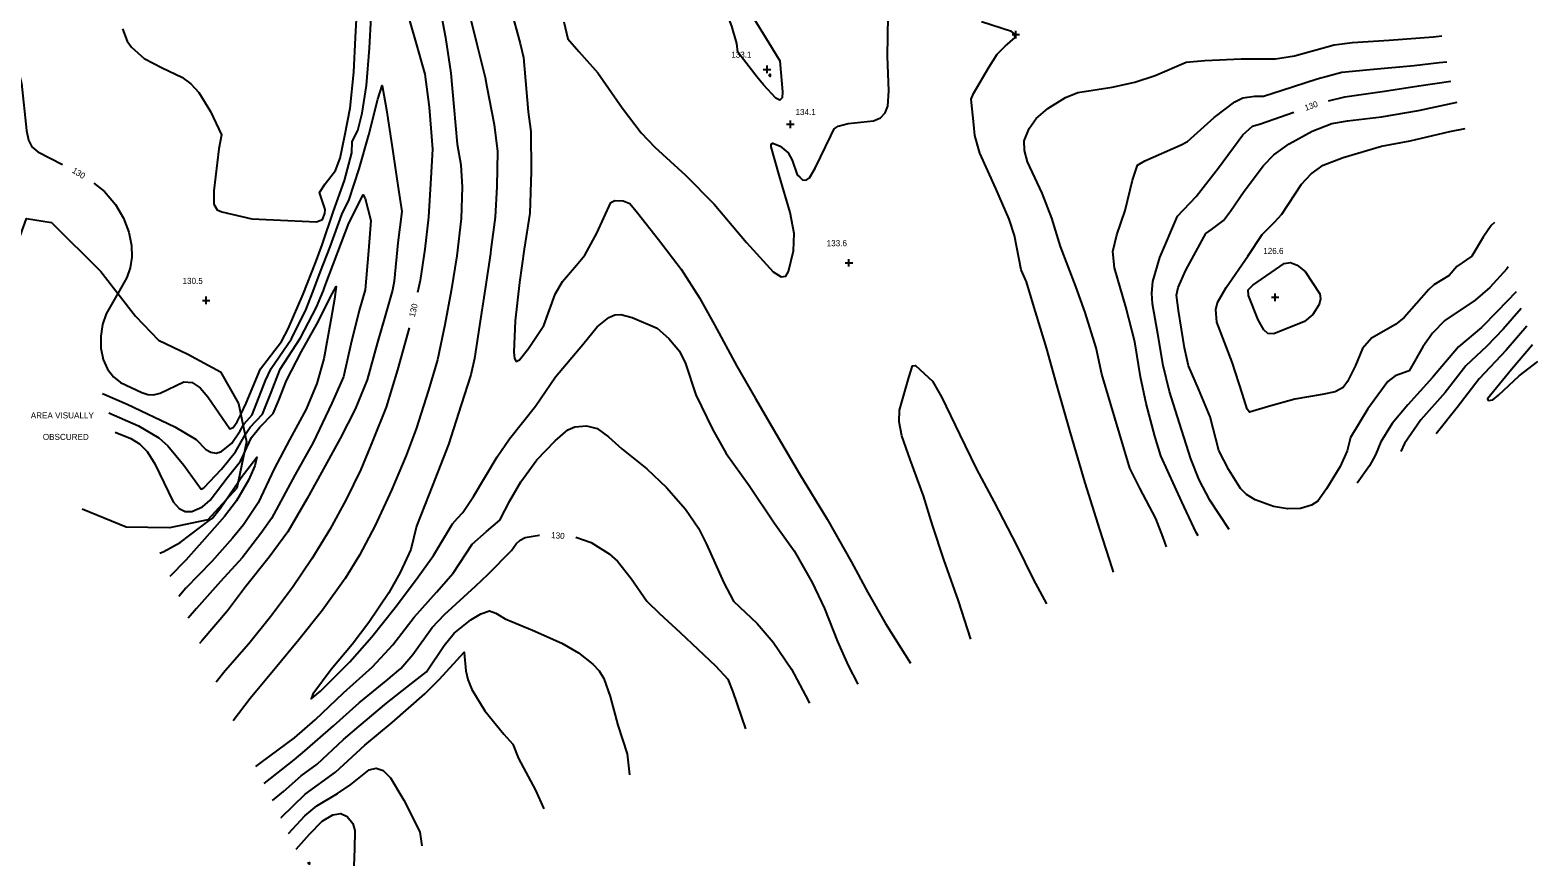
# Model space of a CAD drawing. Extents: x 1475150 to 2003689, y 770235 to 1112803.
# Drawn here: x 2002493.7 to 2002991.4, y 770562.1 to 770837.9 of the extents above; entities that cross this region are included whole.
import ezdxf

# ---------------------------------------------------------------- set-up
doc = ezdxf.new("R2010")
doc.units = 0
for name, color, linetype in [('RD_DTM_Major1', 7, 'Continuous'), ('RD_DTM_Major1_Lbl', 7, 'Continuous'), ('RD_DTM_Major2', 7, 'Continuous'), ('RD_DTM_Minor1', 7, 'Continuous'), ('RD_DTM_Minor2', 7, 'Continuous'), ('RD_DTM_Obscure', 7, 'Continuous'), ('RD_DTM_Spot_Elev', 7, 'Continuous'), ('RD_TX_Misc1', 7, 'Continuous')]:
    doc.layers.add(name, color=color, linetype=linetype)

msp = doc.modelspace()

# ---------------------------------------------------------------- linework, layer by layer
at = {"layer": 'RD_DTM_Major1'}
for points in [[(2002465.72, 770861.55), (2002468.59, 770858.95), (2002472.79, 770853.64), (2002478.26, 770844), (2002482.78, 770837.46), (2002487.68, 770830.27), (2002489.58, 770825.77), (2002490.82, 770820.44), (2002492.47, 770804.83), (2002493.14, 770801.64), (2002494.31, 770799.47), (2002496.27, 770797.81), (2002504.44, 770793.62)], [(2002563.25, 770711.12), (2002565.02, 770714.78), (2002569.71, 770726.13), (2002576.65, 770735.2), (2002578.88, 770739.39), (2002583.81, 770750.77), (2002587.92, 770761.13), (2002590.06, 770767.11), (2002593.86, 770778.22), (2002597.49, 770788.32), (2002599.88, 770797.47), (2002600.05, 770801.23), (2002601.83, 770804.88), (2002603.35, 770810.59), (2002604.73, 770819.72), (2002605.7, 770831.98), (2002606.26, 770842.36)], [(2002617.72, 770845.32), (2002620.86, 770834.63), (2002624.02, 770823.43), (2002625.4, 770812.48), (2002626.48, 770798.68), (2002625.98, 770789.07), (2002625.17, 770776.26), (2002624.04, 770765.63), (2002622.5, 770755.28), (2002621.63, 770751.31)], [(2002922.31, 770814.62), (2002927.69, 770815.95), (2002940.76, 770817.81), (2002952.06, 770819.59), (2002962.64, 770821.09)], [(2002889.51, 770673.17), (2002883.12, 770682.8), (2002879.63, 770689.56), (2002876.8, 770696.44), (2002873.16, 770708.19), (2002869.86, 770718.64), (2002867.73, 770727.25), (2002865.96, 770737.69), (2002864.17, 770747.58), (2002863.96, 770751.18), (2002864.27, 770754.99), (2002866.58, 770762.96), (2002872.44, 770776.59), (2002878.56, 770783.06), (2002885.93, 770792.51), (2002894.01, 770803.41), (2002897.2, 770806.21), (2002899.9, 770807.07), (2002906.4, 770809.32), (2002910.89, 770810.93)], [(2002514.75, 770787.49), (2002518.22, 770784.71), (2002521.88, 770780.45), (2002524.53, 770775.86), (2002526.25, 770771.23), (2002527.12, 770766.86), (2002527.23, 770762.98), (2002526.69, 770759.51), (2002525.62, 770756.36), (2002522.64, 770751.01)], [(2002984.23, 770751.58), (2002978.01, 770745.04), (2002972.83, 770739.83), (2002965.25, 770733.42), (2002960.88, 770728.34), (2002956.64, 770723.25), (2002948.43, 770714.26), (2002943.3, 770708.14), (2002939.54, 770702.04), (2002937.82, 770697.79), (2002935.86, 770694.12), (2002931.76, 770688.38)], [(2002618.78, 770739.65), (2002618.5, 770738.49), (2002615.03, 770725.84), (2002611.23, 770713.47), (2002606.69, 770702.3), (2002602.91, 770692.95), (2002597.98, 770682.98), (2002592.63, 770673.16), (2002586.72, 770663.45), (2002580.27, 770654.01), (2002573.06, 770644.26), (2002565.87, 770635.35), (2002558.06, 770626.45), (2002555.13, 770622.75)], [(2002570.96, 770589.25), (2002580.87, 770597.05), (2002584.36, 770600.1), (2002593.8, 770608.32), (2002602.36, 770615.94), (2002611.21, 770623.19), (2002616.06, 770627.26), (2002620.03, 770631.82), (2002626.41, 770640.73), (2002630.49, 770645.06), (2002640.71, 770654.39), (2002644.86, 770658.36), (2002652.59, 770666.21), (2002654.2, 770668.44), (2002655.45, 770669.58), (2002657.13, 770670.48), (2002661.78, 770671.23), (2002661.89, 770671.23)], [(2002673.87, 770670.57), (2002678.86, 770668.78), (2002684.82, 770665.12), (2002687.6, 770662.68), (2002692.13, 770656.98), (2002697.33, 770649.49), (2002701.45, 770645.39), (2002708.3, 770639.12), (2002719.94, 770628.17), (2002723.98, 770623.72), (2002725.68, 770619.5), (2002729.82, 770607.35)], [(2002585.26, 770562.99), (2002585.95, 770563.26), (2002585.78, 770562.42)]]:
    msp.add_lwpolyline(points, dxfattribs=at)
at = {"layer": 'RD_DTM_Major2'}
msp.add_lwpolyline([(2002522.64, 770751.01), (2002522.33, 770750.46), (2002518.83, 770744.31), (2002517.6, 770740.83), (2002517.01, 770736.99), (2002517.09, 770733.02), (2002517.83, 770729.26), (2002519.21, 770726.01), (2002521.19, 770723.52), (2002523.56, 770721.68), (2002530.6, 770718.3), (2002532.54, 770717.68), (2002534.48, 770717.54), (2002536.59, 770718.08), (2002544.44, 770721.82), (2002547.21, 770721.64), (2002549.88, 770719.85), (2002552.33, 770716.94), (2002559.67, 770706.33), (2002560.72, 770706.81), (2002562.09, 770708.7), (2002563.25, 770711.12)], dxfattribs=at)
at = {"layer": 'RD_DTM_Minor1'}
for points in [[(2002733.66, 770822.46), (2002727.28, 770830.71), (2002726.97, 770833.49), (2002725.31, 770839.24), (2002720.81, 770851.06), (2002716.15, 770863.55), (2002714.46, 770869.94), (2002714.39, 770871.74), (2002714.85, 770872.46), (2002715.79, 770871.99), (2002718.91, 770867.69), (2002724.33, 770857.65), (2002730.87, 770844.67), (2002738.41, 770832.36), (2002741.23, 770827.87), (2002742.1, 770817.58), (2002741.93, 770815.65), (2002741.22, 770814.83), (2002739.84, 770815.51), (2002735.81, 770819.85), (2002733.66, 770822.46)], [(2002524.2, 770838.4), (2002525.73, 770834.31), (2002527.13, 770832.32), (2002531.38, 770828.61), (2002537.26, 770825.56), (2002543.79, 770822.4), (2002546.8, 770820.19), (2002549.4, 770817.36), (2002553.3, 770811.13), (2002556.88, 770803.37), (2002556.04, 770798.8), (2002554.4, 770784.87), (2002554.39, 770780.55), (2002555.48, 770778.68), (2002556.99, 770777.93), (2002566.87, 770775.64), (2002578.77, 770775.07), (2002588.26, 770774.67), (2002590.18, 770775.47), (2002591.03, 770777.38), (2002591.07, 770778.77), (2002589.27, 770784.37), (2002591.1, 770787.27), (2002594.54, 770791.6), (2002596.03, 770795.65), (2002597.59, 770803.14), (2002599.32, 770812.16), (2002600.58, 770824.09), (2002601.09, 770835.53), (2002601.72, 770847.48)], [(2002628.75, 770846.52), (2002630.82, 770835.53), (2002632.56, 770823.79), (2002633.53, 770812.59), (2002634.62, 770800.37), (2002635.85, 770793.54), (2002636.34, 770786.11), (2002636.02, 770775.73), (2002634.57, 770763.49), (2002632.67, 770751.91), (2002630.59, 770740.69), (2002628.16, 770729.17), (2002625.24, 770719.1), (2002621.18, 770706.4), (2002617.84, 770697.56), (2002613, 770686.15), (2002607.65, 770674.42), (2002602.47, 770664.7), (2002597.72, 770656.92), (2002590.24, 770646.46), (2002582.46, 770636.71), (2002574.59, 770627.2), (2002566.3, 770617.39), (2002560.78, 770609.94)], [(2002638.66, 770843.59), (2002641.15, 770833.27), (2002643.92, 770822.31), (2002644.47, 770819.21), (2002646.86, 770806.85), (2002647.95, 770797.88), (2002647.76, 770786.3), (2002647.21, 770776.26), (2002645.8, 770765.54), (2002645.65, 770764.28), (2002643.89, 770752.53), (2002642.03, 770740.49), (2002640.37, 770729.53), (2002639.13, 770724.14), (2002636.03, 770714.29), (2002631.77, 770701.14), (2002626.58, 770687.66), (2002621.29, 770674.2), (2002619.34, 770666.47), (2002615.9, 770658.93), (2002612.13, 770652.22), (2002605.56, 770642.38), (2002599.98, 770635.2), (2002593.12, 770626.91), (2002587.06, 770618.75), (2002586.46, 770617.18), (2002589.59, 770619.8), (2002599.19, 770629.47), (2002606.48, 770637.75), (2002614.22, 770647.43), (2002621.29, 770656.74), (2002626.91, 770664.53), (2002633.18, 770675.03), (2002634.81, 770676.82), (2002636.51, 770678.69), (2002640.02, 770683.98), (2002647.86, 770697.08), (2002652, 770703.04), (2002660.49, 770713.8), (2002667.18, 770723.56), (2002676.2, 770734.21), (2002680.91, 770740), (2002684.69, 770743.13), (2002686.67, 770743.96), (2002688.65, 770744.12), (2002692.45, 770743.14), (2002700.67, 770739.56), (2002704.55, 770736.22), (2002708.01, 770731.99), (2002710.04, 770727.88), (2002713.41, 770717.63), (2002718.94, 770706.27), (2002723.52, 770698.22), (2002731.08, 770687.61), (2002739.34, 770675.33), (2002745.91, 770666.04), (2002751.82, 770655.64), (2002755.94, 770647.08), (2002760.21, 770636.19), (2002763.71, 770628.26), (2002766.88, 770622.06)], [(2002652.28, 770845.24), (2002655.46, 770833.5), (2002656.56, 770828.97), (2002657.24, 770821.17), (2002658.12, 770811), (2002659.03, 770804.47), (2002659.1, 770791.33), (2002658.61, 770777.58), (2002656.83, 770765.7), (2002655.25, 770754.65), (2002653.78, 770741.97), (2002653.33, 770731.63), (2002653.56, 770729.55), (2002654.19, 770728.61), (2002655.28, 770729.16), (2002658.18, 770732.85), (2002663.3, 770740.46), (2002667.06, 770750.75), (2002669.44, 770755.01), (2002674.02, 770760.39), (2002676.83, 770763.73), (2002680.77, 770770.94), (2002685.4, 770781.05), (2002686.7, 770781.72), (2002689.42, 770781.6), (2002691.72, 770780.69), (2002694.22, 770777.7), (2002701.17, 770768.86), (2002708.6, 770759.11), (2002714.69, 770749.58), (2002719.65, 770740.68), (2002727, 770727.06), (2002733.18, 770716.41), (2002739.87, 770704.84), (2002747.69, 770691.51), (2002756.85, 770676.53), (2002764.74, 770662.52), (2002770.25, 770652.33), (2002776.08, 770642.15), (2002784.31, 770628.99)], [(2002669.85, 770840.66), (2002671.24, 770835.1), (2002674.86, 770830.92), (2002681.12, 770823.87), (2002689.13, 770812.34), (2002695.39, 770804.07), (2002699.92, 770799.31), (2002710.06, 770790.1), (2002719.48, 770780.48), (2002730.16, 770767.86), (2002738.93, 770758.18), (2002741.58, 770756.49), (2002743.17, 770756.74), (2002744.09, 770758.27), (2002745.73, 770765.11), (2002745.92, 770770.78), (2002744.63, 770777.8), (2002740.95, 770790.05), (2002738.27, 770799.46), (2002738.36, 770800.32), (2002738.89, 770800.64), (2002741.28, 770799.67), (2002743.92, 770797.46), (2002745.26, 770795.04), (2002746.93, 770790.22), (2002747.8, 770789.42), (2002748.71, 770788.54), (2002749.88, 770788.43), (2002750.98, 770789.21), (2002752.88, 770792.44), (2002758.07, 770803.07), (2002759.07, 770805.35), (2002760.43, 770806.31), (2002763.69, 770807.13), (2002772.09, 770807.99), (2002774.45, 770808.99), (2002775.99, 770810.69), (2002776.82, 770812.91), (2002777.17, 770817.96), (2002776.71, 770829.22), (2002776.95, 770842.66)], [(2002851.27, 770659.08), (2002851, 770660.16), (2002846.78, 770673.13), (2002841.94, 770688.53), (2002837.08, 770705.01), (2002832.77, 770720.43), (2002829.21, 770733.12), (2002824.79, 770747.51), (2002822.61, 770754.84), (2002820.84, 770758.83), (2002818.64, 770770.14), (2002816.92, 770775.61), (2002812.45, 770785.65), (2002807.22, 770797.35), (2002805.5, 770803.19), (2002805.21, 770806.73), (2002804.31, 770815.16), (2002805.11, 770817), (2002810.27, 770825.82), (2002812.93, 770830.04), (2002815.52, 770832.66), (2002818.85, 770835.51), (2002818.6, 770836.75), (2002817.68, 770837.54), (2002807.74, 770840.67)], [(2002868.82, 770667.4), (2002867.72, 770670.48), (2002865.33, 770676.72), (2002859.97, 770686.77), (2002856.69, 770693.42), (2002853.3, 770704.76), (2002850.19, 770715.2), (2002847.49, 770724.35), (2002845.64, 770733.09), (2002841.92, 770744.74), (2002838.86, 770753.33), (2002833.83, 770766.54), (2002830.99, 770775.84), (2002827.82, 770784.11), (2002822.9, 770794.5), (2002821.91, 770798.2), (2002821.88, 770801.45), (2002823.51, 770805.45), (2002825.82, 770808.76), (2002829.69, 770812.06), (2002835.5, 770815.73), (2002839.58, 770817.36), (2002850.91, 770819.1), (2002858.38, 770820.73), (2002865.03, 770822.99), (2002875.26, 770827.42), (2002881.46, 770827.94), (2002893.51, 770828.47), (2002899.63, 770828.45), (2002904.77, 770828.43), (2002911.05, 770829.48), (2002924.21, 770833.07), (2002930.24, 770833.89), (2002942.32, 770834.64), (2002956.91, 770835.76), (2002959.65, 770836.1)], [(2002879.23, 770671.02), (2002878.66, 770672.15), (2002873.88, 770682.31), (2002866.9, 770697.44), (2002865, 770703.93), (2002862.09, 770714.74), (2002860.21, 770723.47), (2002858.33, 770735.1), (2002855.34, 770746.65), (2002851.6, 770759.52), (2002851.12, 770764.84), (2002852.42, 770770.36), (2002855.12, 770778.46), (2002857.56, 770788.39), (2002859.27, 770793.35), (2002861.7, 770794.81), (2002873.65, 770800.12), (2002875.79, 770801.19), (2002884.51, 770809.11), (2002891.36, 770814.34), (2002894.06, 770815.64), (2002897.94, 770816.17), (2002900.8, 770816.21), (2002907.05, 770818.13), (2002918.51, 770821.83), (2002926.66, 770824.09), (2002937.11, 770825.04), (2002950.56, 770826.31), (2002958.87, 770827.31), (2002961.36, 770827.51)], [(2002737.62, 770823.19), (2002738.03, 770823.37), (2002738.02, 770822.7), (2002737.62, 770823.19)], [(2002564, 770707.45), (2002564.34, 770708.02), (2002566.96, 770711.02), (2002571.39, 770722.29), (2002573.25, 770726.28), (2002579.97, 770736.1), (2002584.81, 770745.85), (2002587.17, 770751.75), (2002589.54, 770758.25), (2002592.77, 770766.45), (2002596.56, 770777.15), (2002599.05, 770782.1), (2002602.33, 770792.13), (2002605.57, 770803.41), (2002608.45, 770815.17), (2002609.93, 770819.67), (2002611.3, 770811.6), (2002613.15, 770800.07), (2002615.13, 770786.63), (2002616.43, 770778.04), (2002615.1, 770767.74), (2002613.93, 770755.13), (2002613.35, 770752.11), (2002610.93, 770743.7), (2002608.25, 770734.48), (2002604.93, 770722.58), (2002600.99, 770712.82), (2002596.1, 770703.15), (2002591.14, 770694.17), (2002585.2, 770683.31), (2002578.83, 770672.34), (2002572.6, 770663.95), (2002564.82, 770654.23), (2002558.88, 770646.32), (2002550.5, 770636.45), (2002549.57, 770635.46)], [(2002981.65, 770759.87), (2002981.17, 770759.15), (2002975.53, 770753.01), (2002970.69, 770748.87), (2002960.66, 770742.1), (2002956.59, 770737.88), (2002953.38, 770733.46), (2002948.92, 770725.46), (2002944.3, 770723.88), (2002941.84, 770722), (2002935.23, 770712.96), (2002929.5, 770703.48), (2002928.41, 770699.08), (2002926.17, 770693.97), (2002921.66, 770686.56), (2002918.81, 770682.45), (2002916.64, 770681.17), (2002913.08, 770680.1), (2002908.71, 770679.91), (2002904.11, 770680.73), (2002898.08, 770682.92), (2002895.17, 770684.66), (2002893.21, 770686.61), (2002889.39, 770692.86), (2002886.05, 770699.25), (2002883.25, 770710.31), (2002879.33, 770719.53), (2002876.1, 770727.19), (2002874.81, 770733.12), (2002872.76, 770745.38), (2002872.09, 770750.43), (2002872.62, 770753.01), (2002875.24, 770758.72), (2002881.78, 770770.81), (2002883.67, 770772.19), (2002887.6, 770775.09), (2002889.95, 770778.21), (2002894.43, 770784.81), (2002900.88, 770793.25), (2002904.29, 770796.83), (2002909.35, 770800.43), (2002916.94, 770804.64), (2002923.41, 770807.12), (2002928.6, 770807.98), (2002939.79, 770809.3), (2002951.96, 770811.46), (2002964.74, 770814.21)], [(2002977.11, 770774.46), (2002976.01, 770773.44), (2002973.39, 770769.58), (2002969.61, 770763.32), (2002964.7, 770759.95), (2002962.1, 770756.99), (2002957.11, 770753.86), (2002955.4, 770752.32), (2002947.29, 770743.07), (2002944.41, 770740.8), (2002936.48, 770736.3), (2002933.48, 770732.9), (2002931.16, 770727.3), (2002928.61, 770722.02), (2002927.09, 770720.05), (2002924.51, 770718.58), (2002920.15, 770717.7), (2002911.21, 770716.16), (2002902.47, 770713.76), (2002896.26, 770711.88), (2002895.45, 770712.88), (2002893.85, 770717.82), (2002890.52, 770728.37), (2002885.46, 770741.51), (2002885.06, 770745.76), (2002885.66, 770748.03), (2002888.48, 770753.04), (2002895.67, 770763.4), (2002900.4, 770770.47), (2002904.49, 770774.6), (2002906.88, 770777.25), (2002913.4, 770787.11), (2002916.56, 770790.57), (2002920.55, 770793.36), (2002927.12, 770795.87), (2002939.74, 770799.66), (2002949.28, 770801.45), (2002962.29, 770804.45), (2002967.44, 770805.53)], [(2002564.65, 770704.33), (2002564.77, 770704.55), (2002566.33, 770706.94), (2002570.47, 770711.21), (2002573.32, 770718.32), (2002576.26, 770726.09), (2002583.01, 770736.36), (2002588.19, 770746.52), (2002590.51, 770752.03), (2002590.94, 770753.32), (2002595.28, 770764.62), (2002598.9, 770774.25), (2002603.7, 770783.61), (2002604.36, 770782.37), (2002606.19, 770775.14), (2002605.43, 770765.09), (2002604.32, 770752.25), (2002602.33, 770745.42), (2002599.6, 770734.33), (2002597.11, 770723.56), (2002593.35, 770714.79), (2002587.19, 770701.86), (2002581.14, 770691.03), (2002573.42, 770676.81), (2002569.92, 770671.79), (2002563.67, 770663.72), (2002556.54, 770655.97), (2002548.63, 770647.03), (2002545.9, 770643.84)], [(2002897.28, 770753.77), (2002907.64, 770760.88), (2002909.76, 770761.23), (2002911.99, 770760.41), (2002914.62, 770758.34), (2002919.42, 770750.86), (2002919.61, 770749.21), (2002919.22, 770747.44), (2002917.16, 770744.06), (2002914.36, 770741.81), (2002904.21, 770737.67), (2002902.3, 770737.8), (2002900.91, 770739), (2002899.08, 770742.34), (2002895.9, 770750.38), (2002895.82, 770752.25), (2002897.28, 770753.77)], [(2002564.27, 770698.04), (2002565.27, 770700.18), (2002566.83, 770703.54), (2002569.53, 770706.95), (2002573.99, 770711.4), (2002575.82, 770715.78), (2002578.31, 770722.34), (2002583.31, 770731.93), (2002588.32, 770740.85), (2002593.44, 770750.95), (2002594.76, 770753.36), (2002594.18, 770749.19), (2002593.1, 770742.85), (2002590.65, 770729.42), (2002588.39, 770721.28), (2002584.85, 770712.87), (2002579.3, 770702.71), (2002574.27, 770693.18), (2002568.96, 770681.9), (2002564.14, 770674.69), (2002560.55, 770670.28), (2002553.69, 770662.6), (2002545.16, 770653.81), (2002542.77, 770650.99)], [(2002985.94, 770746.07), (2002980, 770739.2), (2002974.51, 770733.69), (2002967.63, 770727.14), (2002960.76, 770718.38), (2002952.74, 770709.27), (2002947.33, 770701.5), (2002946.2, 770698.9)], [(2002987.77, 770740.21), (2002980.9, 770732.32), (2002972.04, 770722.87), (2002964.72, 770713.45), (2002957.88, 770704.74)], [(2002989.66, 770734.12), (2002982.73, 770725.94), (2002974.79, 770716.27), (2002975.03, 770715.72), (2002976.55, 770715.89), (2002978.42, 770717.48), (2002985.26, 770723.82), (2002991.39, 770728.55)], [(2002804.22, 770636.89), (2002800.16, 770649.62), (2002795.36, 770663.2), (2002791.56, 770674.51), (2002788.59, 770684.25), (2002784.16, 770696.2), (2002781.44, 770704.09), (2002780.59, 770708.71), (2002780.71, 770712.5), (2002783.74, 770723.34), (2002784.95, 770727.14), (2002785.98, 770727.27), (2002791.57, 770722.08), (2002794.69, 770716.7), (2002800.44, 770704.56), (2002806.14, 770693.02), (2002811.8, 770682.35), (2002819.43, 770667.72), (2002824.83, 770656.73), (2002829.17, 770648.6)], [(2002568.18, 770594.9), (2002569.93, 770596.17), (2002580.96, 770604.31), (2002587.78, 770610.31), (2002597.17, 770619.2), (2002606.72, 770627.74), (2002613.47, 770635.03), (2002620.52, 770644.14), (2002627.9, 770652.41), (2002633.35, 770658.76), (2002639.59, 770668.31), (2002644.33, 770672.44), (2002648.81, 770676.24), (2002652.07, 770682.54), (2002655.66, 770688.91), (2002661, 770696.07), (2002666.99, 770702.38), (2002671.23, 770706), (2002673.51, 770706.99), (2002677.37, 770707.34), (2002680.85, 770706.51), (2002684.62, 770703.67), (2002688.98, 770699.7), (2002697.28, 770693.16), (2002703.76, 770687.04), (2002709.99, 770679.81), (2002714.35, 770673.54), (2002716.98, 770668.28), (2002722.65, 770655.53), (2002725.93, 770649.44), (2002733.71, 770642.09), (2002739, 770635.89), (2002745.04, 770627.05), (2002749.69, 770618.37), (2002751.01, 770615.76)], [(2002562.38, 770688.77), (2002563.39, 770690.24), (2002568.56, 770696.97), (2002567.89, 770694.19), (2002565.83, 770689.42), (2002561.81, 770682.63), (2002557.92, 770677.41), (2002551.31, 770669.94), (2002545.15, 770663.02), (2002539.88, 770657.61)], [(2002536.53, 770665.26), (2002537.9, 770665.84), (2002543.23, 770668.86), (2002552.85, 770676.05), (2002553.75, 770676.78), (2002556.39, 770680.08), (2002558.08, 770682.52)], [(2002573.69, 770583.69), (2002577.32, 770586.64), (2002583.23, 770591.84), (2002588.49, 770595.72), (2002597.18, 770603.84), (2002602.27, 770608.19), (2002611.39, 770615.78), (2002619.55, 770622.27), (2002624.59, 770626.13), (2002630.41, 770634.87), (2002633.72, 770638.86), (2002639.13, 770643.36), (2002642.44, 770645.34), (2002645.31, 770646.23), (2002647.41, 770645.53), (2002650.52, 770643.67), (2002659.56, 770639.92), (2002669.2, 770635.63), (2002674.68, 770632.43), (2002679.51, 770628.71), (2002681.52, 770626.5), (2002683.13, 770623.98), (2002685.19, 770617.99), (2002687.76, 770608.52), (2002690.75, 770599.07), (2002691.53, 770592.14)], [(2002576.47, 770578.04), (2002576.56, 770578.11), (2002584.55, 770585.77), (2002594.55, 770593.03), (2002604.21, 770601.98), (2002613.18, 770609.42), (2002623.98, 770618.91), (2002628.84, 770623.73), (2002636.95, 770632.66), (2002637.02, 770632.4), (2002637.5, 770626.47), (2002638.19, 770623.57), (2002639.47, 770620.28), (2002643.78, 770613.25), (2002650.11, 770605.58), (2002653, 770602.25), (2002654.91, 770597.58), (2002660.51, 770587.05), (2002663.29, 770580.92)], [(2002579.05, 770572.81), (2002584.4, 770578.58), (2002588.31, 770581.86), (2002595.16, 770586.03), (2002599.58, 770588.92), (2002605.64, 770593.79), (2002607.89, 770594.3), (2002610.27, 770593.53), (2002612.68, 770591.13), (2002617.1, 770583.82), (2002622.4, 770573.33), (2002622.98, 770568.73)], [(2002581.58, 770567.66), (2002585.98, 770572.51), (2002590.08, 770576.85), (2002593.62, 770578.94), (2002596.27, 770579.41), (2002598.34, 770578.35), (2002600.28, 770576.08), (2002600.87, 770573.77), (2002600.83, 770567.74), (2002600.51, 770562.1)]]:
    msp.add_lwpolyline(points, dxfattribs=at)
at = {"layer": 'RD_DTM_Minor2'}
msp.add_line((2002558.08, 770682.52), (2002562.38, 770688.77), dxfattribs=at)
for points in [[(2002517.57, 770718.03), (2002525.75, 770714.55), (2002541.5, 770707.01), (2002548.49, 770702.83), (2002551.73, 770699.56), (2002553.35, 770698.6), (2002555.11, 770698.27), (2002556.92, 770698.83), (2002560.25, 770701.62), (2002562.99, 770705.71), (2002564, 770707.45)], [(2002519.71, 770711.62), (2002529.51, 770707.39), (2002536.22, 770703.34), (2002539.16, 770700.76), (2002544.5, 770694.32), (2002550.2, 770686.47), (2002551.09, 770686.84), (2002556.87, 770693.03), (2002561.49, 770698.72), (2002564.65, 770704.33)], [(2002521.83, 770705.26), (2002526.95, 770703.17), (2002529.81, 770701.42), (2002532.32, 770698.88), (2002534.84, 770694.84), (2002540.95, 770682.25), (2002542.86, 770680.05), (2002544.94, 770679.08), (2002547.04, 770679.09), (2002550.61, 770680.56), (2002553.18, 770682.78), (2002558.8, 770690.15), (2002563.19, 770695.7), (2002564.27, 770698.04)]]:
    msp.add_lwpolyline(points, dxfattribs=at)
at = {"layer": 'RD_DTM_Obscure'}
msp.add_lwpolyline([(2002484.51, 770730.44), (2002489.35, 770743.58), (2002489.28, 770755.61), (2002489.49, 770767.51), (2002492.48, 770775.76), (2002500.75, 770774.44), (2002517.05, 770758.24), (2002528.44, 770743.49), (2002536.12, 770735.62), (2002545.72, 770731.05), (2002556.5, 770725.12), (2002562.51, 770714.71), (2002565.1, 770702.1), (2002561.97, 770686.77), (2002552.41, 770676.35), (2002539.69, 770673.67), (2002525.42, 770673.86), (2002510.9, 770679.89)], dxfattribs=at)
at = {"layer": 'RD_DTM_Spot_Elev'}
for p, q in [((2002819.09, 770835.23), (2002819.09, 770837.73)), ((2002817.84, 770836.48), (2002820.34, 770836.48)), ((2002735.7, 770824.99), (2002738.2, 770824.99)), ((2002736.95, 770823.74), (2002736.95, 770826.24)), ((2002744.65, 770805.62), (2002744.65, 770808.12)), ((2002743.4, 770806.87), (2002745.9, 770806.87)), ((2002762.75, 770761.14), (2002765.25, 770761.14)), ((2002764, 770759.89), (2002764, 770762.39)), ((2002550.58, 770748.73), (2002553.08, 770748.73)), ((2002551.83, 770747.48), (2002551.83, 770749.98)), ((2002903.44, 770749.78), (2002905.94, 770749.78)), ((2002904.69, 770748.53), (2002904.69, 770751.03))]:
    msp.add_line(p, q, dxfattribs=at)

# ---------------------------------------------------------------- texts
at = {"layer": 'RD_DTM_Major1_Lbl'}
for rotation, p in [(19.7555, (2002914.79, 770811.27)), (328.5606, (2002507.33, 770791.08)), (76.1773, (2002620.66, 770743.09)), (355.2739, (2002665.62, 770670.32))]:
    msp.add_text('130', height=2, rotation=rotation, dxfattribs=at).set_placement(p)
at = {"layer": 'RD_DTM_Spot_Elev'}
for s, p in [('133.1', (2002725.14, 770828.86)), ('134.1', (2002746.35, 770809.92)), ('133.6', (2002756.65, 770766.63)), ('126.6', (2002900.75, 770764.08)), ('130.5', (2002544.02, 770754.19))]:
    msp.add_text(s, height=2, dxfattribs=at).set_placement(p)
at = {"layer": 'RD_TX_Misc1'}
for s, p in [('AREA VISUALLY', (2002493.93, 770709.79)), ('OBSCURED', (2002497.91, 770702.69))]:
    msp.add_text(s, height=2, dxfattribs=at).set_placement(p)

doc.saveas('drawing.dxf')
